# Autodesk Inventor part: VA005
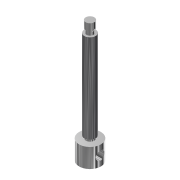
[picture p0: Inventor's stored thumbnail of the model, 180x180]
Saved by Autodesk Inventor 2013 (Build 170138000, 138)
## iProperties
Manager: P MOLLOY
Company: NUIG
Shininess: 64.0
Length Units: 11269
Angle Units: 11279
Time Units: 11290
Mass Units: 11283
Length Display Precision: 3
Angle Display Precision: 2
Compacted: True
Part Number: VA005
Document SubType Name: Modeling
Created: 2004-12
Designer: warren davies
Manufacturer: Standard
Standards Organization: Custom
Material: Steel, Mild
Density: 7.86 g/cm^3
Density: 0.0
Volumn: 0.0
Area: 0.0
PropertySet Name: Model Information
Control State: 0
Master: False
Checked Out: False
Title: CLAMP SCREW
Subject: VICE ASSEMBLY
Author: warren davies
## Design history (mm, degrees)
sketch "Sketch1"
  geometry: C1 r 12.5 at (0, 0)
  constraints: 1 centre point
  dimensions: "d0" = 25 diameter of C1
extrude "Extrusion1" new body sketch "Sketch1" distance "d1" = 22; taper "d2" = 0 deg
sketch "Sketch2"
  geometry: C1 r 12.5 at (0, 0) reference; C2 r 5 at (0, 0)
  constraints: 1 centre point, 1 coincident
  dimensions: "d3" = 10 diameter of C2
extrude "Extrusion2" join sketch "Sketch2" distance "d4" = 3; taper "d5" = 0 deg
sketch "Sketch3"
  geometry: C1 r 5 at (0, 0) reference; C2 r 6.5 at (0, 0)
  constraints: 1 centre point, 1 coincident
  dimensions: "d6" = 13 diameter of C2
extrude "Extrusion3" join sketch "Sketch3" distance "d7" = 102; taper "d8" = 0 deg
sketch "Sketch4"
  geometry: C1 r 6.5 at (0, 0) reference; C2 r 4 at (0, 0)
  constraints: 1 centre point, 1 coincident
  dimensions: "d9" = 8 diameter of C2
extrude "Extrusion4" join sketch "Sketch4" distance "d10" = 5; taper "d11" = 0 deg
sketch "Sketch5"
  geometry: C1 r 6.5 at (0, 0) reference; C2 r 5 at (0, 0)
  constraints: 1 centre point, 1 coincident
  dimensions: "d12" = 10 diameter of C2
extrude "Extrusion5" join sketch "Sketch5" distance "d13" = 8; taper "d14" = 0 deg
workplane "Work Plane1"
sketch "Sketch6"
  geometry: L1 (-5, 8)-(5, 8) reference; C1 r 1.5 at (0, 0)
  constraints: 1 centre point
  dimensions: "d15" = 3 diameter of C1; "d16" = 8 distance from line of C1.centre L1; "d17" = 5 horizontal distance of C1.centre L1.start
extrude "Extrusion6" cut sketch "Sketch6" stored distance "d18" = 8; taper "d19" = 0 deg
workplane "Work Plane2"
sketch "Sketch7"
  geometry: L1 (-12.5, 0)-(12.5, 0) reference; C1 r 5 at (0, 11)
  constraints: 1 centre point
  dimensions: "d20" = 10 diameter of C1; "d21" = 11 distance from line of L1 C1.centre; "d22" = 12.5 horizontal distance of C1.centre L1.start
extrude "Extrusion7" cut sketch "Sketch7" stored distance "d23" = 8; taper "d24" = 0 deg
thread "Thread1" dims "d25" = 10, "d26" = 0
body "Solid1"
